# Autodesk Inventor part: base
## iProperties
Created: 2008-03
Part Number: base
Document SubType Name: Modeling
Designer: t-ikumi
Density: 1 g/cm^3
Author: t-ikumi
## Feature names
1. 押し出し1 [Extrusion]
2. 押し出し2 [Extrusion]
